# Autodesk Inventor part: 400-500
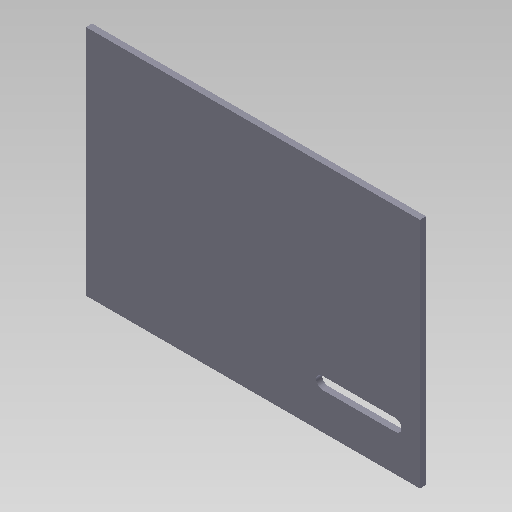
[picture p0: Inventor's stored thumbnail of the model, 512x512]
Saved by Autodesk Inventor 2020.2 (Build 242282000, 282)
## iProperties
Created: 2010-10
Part Number: 400-500
Document SubType Name: Modeling
Designer: F.Stasiak
Density: 0.55 g/cm^3
Material: MDF
Description: =Drzwiczki z otworem <d0> x <d9>
Mass: 1131.31 g
Surface Area: 4329.74 cm^2
Volume: 2056.93 cm^3
Appearance: Mleczny
Company: Fabian Stasiak CAD Consulting
Manager: www.cadconsulting.pl
d0: 547
d9: 381
Author: F.Stasiak
Subject: Zbiór ćwiczeń. Autodesk Inventor 2020. Kurs podstawowy
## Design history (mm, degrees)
sketch "Szkic1"
  geometry: L1 (0, 0)-(547, 0); L2 (547, 0)-(547, 381); L3 (547, 381)-(0, 381); L4 (0, 381)-(0, 0)
  constraints: 8 end point, 2 parallel, 1 horizontal, 1 perpendicular
  dimensions: "d0" = 547 distance of L2.end L3.end; "d9" = 381 distance of L1.end L2.end (derived)
extrude "Wyciągnięcie proste1" new body sketch "Szkic1" distance "d1" = 10; taper "d2" = 0 deg
sketch "Szkic2"
  geometry: L1 (387, 60)-(507, 60); L2 (507, 80)-(387, 80); L3 (547, 0)-(0, 0) reference; L4 (547, 381)-(547, 0) reference; A1 r 10 centre (507, 70) between (507, 60) and (507, 80); A2 r 10 centre (387, 70) between (387, 80) and (387, 60)
  constraints: 4 end point, 4 point on circle, 4 tangent, 2 centre point, 1 horizontal, 1 parallel
  dimensions: "d3" = 10 radius of A1; "d4" = 120 distance of L1.start L1.end; "d5" = 60 distance between parallel lines of L3 L1; "d6" = 40 distance from line of L4 A1.centre
extrude "Wyciągnięcie proste2" cut sketch "Szkic2" extent not by distance; stored distance "d7" = 10; taper "d8" = 0 deg
node "Bryła1"
